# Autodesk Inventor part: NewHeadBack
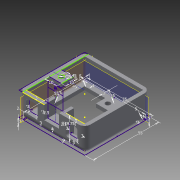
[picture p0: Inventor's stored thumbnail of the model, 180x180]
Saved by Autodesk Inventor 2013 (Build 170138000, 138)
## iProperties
Created: 2013-04
Part Number: NewHeadBack
Material: Generic
Document SubType Name: Modeling
Designer: frankenteddy
Density: 1 g/cm^3
Author: frankenteddy
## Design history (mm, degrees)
node "Blocks"
  sketch "Block1"
    geometry: L1 (49.279, 30.472)-(71.779, 30.472); L2 (71.779, 30.472)-(71.779, 18.072); L3 (71.779, 18.072)-(49.279, 18.072); L4 (49.279, 18.072)-(49.279, 30.472); L5 (49.279, 30.472)-(44.779, 30.472); L6 (44.779, 30.472)-(44.779, 18.072); L7 (44.779, 18.072)-(49.279, 18.072); L8 (49.279, 18.072)-(49.279, 30.472); L9 (71.779, 30.472)-(76.279, 30.472); L10 (76.279, 30.472)-(76.279, 18.072); L11 (76.279, 18.072)-(71.779, 18.072); L12 (71.779, 18.072)-(71.779, 30.472); L13 (44.779, 24.272)-(76.279, 24.272); L14 (60.529, 30.472)-(60.529, 18.072); L15 (47.029, 30.472)-(47.029, 18.072); L16 (74.029, 30.472)-(74.029, 18.072); C1 r 1.1 at (47.029, 24.272); C2 r 1.1 at (74.029, 24.272); 1 further point
    constraints: 32 end point, 8 midpoint, 6 parallel, 3 horizontal, 3 perpendicular, 2 centre point, 2 point on line
    dimensions: "d9" = 22.5 distance of L2.end L3.end; "d10" = 12.4 distance of L1.end L2.end; "d11" = 4.5 distance of L7.end L6.end; "d12" = 4.5 distance of L10.end L11.end; "d13" = 2.2 diameter of C1; "d14" = 2.2 diameter of C2; "d15" = 2.25 distance between parallel lines of L10 L16
sketch "Sketch1"
  geometry: L1 (-27.5, 27.5)-(27.5, 27.5); L2 (27.5, 27.5)-(27.5, -27.5); L3 (27.5, -27.5)-(-27.5, -27.5); L4 (-27.5, -27.5)-(-27.5, 27.5); L5 (-24.5, 24.5)-(24.5, 24.5); L6 (24.5, 24.5)-(24.5, -24.5); L7 (24.5, -24.5)-(-24.5, -24.5); L8 (-24.5, -24.5)-(-24.5, 24.5); L9 (-23.5, 27.5)-(-23.5, -27.5); L10 (-27.5, 23.5)-(27.5, 23.5); 5 further points
  constraints: 20 end point, 4 parallel, 4 perpendicular, 4 point on line, 2 coincident, 2 horizontal, 2 midpoint, 1 horizontal alignment, 1 vertical alignment
  dimensions: "d0" = 55 distance of L1.start L1.end; "d2" = 55 distance of L1.end L2.end; "d3" = 3 distance between parallel lines of L5 L1; "d4" = 3 distance between parallel lines of L8 L4; "d5" = 3 distance between parallel lines of L2 L6; "d6" = 3 distance between parallel lines of L3 L7; "d48" = 4 distance between parallel lines of L10 L1; "d49" = 4 distance between parallel lines of L4 L9
extrude "Extrusion1" new body sketch "Sketch1" distance "d7" = 19.75; taper "d8" = 0 deg
sketch "Sketch2"
  geometry: L1 (0, 0)-(49, 0) reference; L2 (49, -19.75)-(0, -19.75) reference; L3 (24.5, -19.75)-(24.5, 0); L4 (15.8, 0)-(15.8, -19.75); L5 (33.2, -19.75)-(33.2, 0); L6 (15.8, -19.75)-(33.2, -19.75); L7 (0, 0)-(0, -19.75) reference; L8 (49, 0)-(49, -19.75) reference; L9 (0, -3)-(15.8, -3); L10 (33.2, -3)-(49, -3); L11 (5, -6)-(10.8, -6); L12 (12.8, -8)-(12.8, -14.75); L13 (10.8, -16.75)-(5, -16.75); L14 (3, -14.75)-(3, -8); L15 (38.2, -6)-(44, -6); L16 (46, -8)-(46, -14.75); L17 (44, -16.75)-(38.2, -16.75); L18 (36.2, -14.75)-(36.2, -8); A1 r 2 centre (5, -8) between (5, -6) and (3, -8); A2 r 2 centre (10.8, -8) between (12.8, -8) and (10.8, -6); A3 r 2 centre (10.8, -14.75) between (10.8, -16.75) and (12.8, -14.75); A4 r 2 centre (5, -14.75) between (3, -14.75) and (5, -16.75); A5 r 2 centre (38.2, -8) between (38.2, -6) and (36.2, -8); A6 r 2 centre (44, -8) between (46, -8) and (44, -6); A7 r 2 centre (44, -14.75) between (44, -16.75) and (46, -14.75); A8 r 2 centre (38.2, -14.75) between (36.2, -14.75) and (38.2, -16.75)
  constraints: 28 end point, 16 point on circle, 16 tangent, 8 centre point, 8 point on line, 7 equal radius, 7 perpendicular, 4 parallel, 2 horizontal, 2 vertical, 1 midpoint
  dimensions: "d16" = 4 dimension on L1; "d17" = 19.75 dimension on L1 (derived); "d18" = 2.5 dimension on L4; "d19" = 2.5 dimension on L5; "d35" = 3 distance between parallel lines of L9 L1; "d36" = 3 distance between parallel lines of L10 L1; "d74" = 3 distance between parallel lines of L11 L9; "d75" = 3 distance between parallel lines of L7 L14; "d76" = 3 distance between parallel lines of L2 L13; "d77" = 3 distance between parallel lines of L4 L12; "d78" = 3 distance between parallel lines of L15 L10; "d79" = 3 distance between parallel lines of L16 L8; "d80" = 3 distance between parallel lines of L17 L2; "d81" = 3 distance between parallel lines of L18 L5; "d82" = 2 radius of A1
  node "Block1:1" dims "d16" = 4, "d17" = 19.75 (derived), "d18" = 2.5, "d19" = 2.5, "d35" = 3, "d36" = 3, "d74" = 3, "d75" = 3, "d76" = 3, "d77" = 3, "d78" = 3, "d79" = 3, "d80" = 3, "d81" = 3, "d82" = 2
extrude "Extrusion2" join sketch "Sketch2" distance "d20" = 7; taper "d21" = 0 deg
extrude "Extrusion3" cut sketch "Sketch2" distance "d22" = 7; taper "d23" = 0 deg
extrude "Extrusion4" cut sketch "Sketch2" distance "d24" = 3; taper "d25" = 0 deg
sketch "Sketch3"
  geometry: L1 (-27.5, -27.5)-(-6.2, -27.5) reference; L2 (-27.5, 27.5)-(-24.5, 27.5); L3 (-24.5, 27.5)-(-24.5, -27.5); L4 (-24.5, -27.5)-(-27.5, -27.5); L5 (-27.5, -27.5)-(-27.5, 27.5); L6 (-27.5, 0)-(0, 0); L7 (-24.5, 5)-(-14.5, 5); L8 (-14.5, 5)-(-14.5, -5); L9 (-14.5, -5)-(-24.5, -5); L10 (-24.5, -5)-(-24.5, 5); L11 (-19.5, 5)-(-19.5, -5); C1 r 2 at (-19.5, 0)
  constraints: 20 end point, 4 midpoint, 4 parallel, 3 perpendicular, 2 horizontal, 2 point on line, 1 centre point
  dimensions: "d26" = 10 distance of L8.end L9.end; "d27" = 10 distance of L7.end L8.end; "d28" = 5 distance between parallel lines of L7 L6; "d29" = 4 diameter of C1
extrude "Extrusion5" join sketch "Sketch3" distance "d30" = 3; taper "d31" = 0 deg
sketch "Sketch4"
  geometry: L1 (24.5, 5)-(14.5, 5); L2 (14.5, 5)-(14.5, -5); L3 (14.5, -5)-(24.5, -5); L4 (24.5, -5)-(24.5, 5); L5 (19.5, 5)-(19.5, -5); L6 (14.5, 0)-(24.5, 0); L7 (19.5, 4.879)-(23.725, 2.439); L8 (23.725, 2.439)-(23.725, -2.439); L9 (23.725, -2.439)-(19.5, -4.879); L10 (19.5, -4.879)-(15.275, -2.439); L11 (15.275, -2.439)-(15.275, 2.439); L12 (15.275, 2.439)-(19.5, 4.879); C1 r 2 at (19.5, 0) reference; 2 further points
  constraints: 24 end point, 4 midpoint, 2 parallel, 1 coincident, 1 horizontal, 1 perpendicular, 1 point on line, 13 other
  dimensions: "d32" = 8.45 distance between parallel lines of L8 L11
extrude "Extrusion7" join sketch "Sketch2" distance "d37" = 5; taper "d38" = 0 deg
sketch "Sketch5"
  geometry: L1 (0, 0)-(-19.75, 0) reference; L2 (0, 49)-(0, 0) reference; L3 (0, 49)-(-19.75, 49) reference; L4 (-3, 49)-(-3, 0); 1 further point
  constraints: 2 end point, 2 point on line, 1 perpendicular
  dimensions: "d39" = 3 distance between parallel lines of L4 L2
extrude "Extrusion8" join sketch "Sketch5" distance "d40" = 5; taper "d41" = 0 deg
sketch "Sketch6"
  geometry: L1 (49, 0)-(0, 0) reference; L2 (49, 0)-(49, 19.75) reference; L3 (0, 0)-(0, 19.75) reference; L4 (0, 3)-(49, 3); 1 further point
  constraints: 2 end point, 2 point on line, 1 perpendicular
  dimensions: "d42" = 3 distance between parallel lines of L4 L1
extrude "Extrusion9" join sketch "Sketch6" distance "d43" = 5; taper "d44" = 0 deg
mirror "Mirror1"
fillet "Fillet5" dims "d69" = 3
fillet "Fillet2" dims "d46" = 5
workplane "Work Plane1"
workplane "Work Plane2"
sketch "Sketch7"
  geometry: L1 (0, 0)-(-55, 0) reference; L2 (-55, 0)-(-55, 1); L3 (-55, 1)-(0, 1); L4 (0, 1)-(0, 0) reference; L5 (-4, 1)-(-4, 0); L6 (-51, 1)-(-51, 0); L7 (-27.5, 1)-(-27.5, 0); L8 (-27.5, 3.5)-(-27.5, -1.5); L9 (-4, 3.5)-(-4, -1.5); L10 (-51, 3.5)-(-51, -1.5); A1 r 2.5 centre (-51, 1) between (-51, 3.5) and (-51, -1.5); A2 r 2.5 centre (-4, 1) between (-4, 3.5) and (-4, -1.5); A3 r 2.5 centre (-27.5, 1) between (-27.5, 3.5) and (-27.5, -1.5)
  constraints: 20 end point, 6 point on circle, 4 parallel, 4 point on line, 3 centre point, 3 coincident, 3 perpendicular, 2 horizontal, 1 collinear, 1 midpoint, 1 vertical
  dimensions: "d51" = 55 distance of L2.end L3.end; "d52" = 1 distance of L1.end L2.end; "d53" = 4 distance between parallel lines of L5 L4; "d54" = 4 distance between parallel lines of L2 L6; "d55" = 5 diameter of A1; "d56" = 5 diameter of A2; "d57" = 5 diameter of A3
sketch "Sketch8"
  geometry: L1 (0, 0)-(-55, 0) reference; L2 (-55, 0)-(-55, 1); L3 (-55, 1)-(0, 1); L4 (0, 1)-(0, 0) reference; L5 (-27.5, 1)-(-27.5, 0); L6 (-27.5, 3.5)-(-27.5, -1.5); A1 r 2.5 centre (-27.5, 1) between (-27.5, 3.5) and (-27.5, -1.5)
  constraints: 12 end point, 2 horizontal, 2 parallel, 2 point on circle, 1 centre point, 1 coincident, 1 collinear, 1 midpoint, 1 perpendicular, 1 vertical
  dimensions: "d61" = 55 distance of L2.end L3.end; "d62" = 1 distance of L1.end L2.end; "d63" = 5 diameter of A1
extrude "Extrusion10" cut sketch "Sketch2" distance "d65" = 6; taper "d66" = 0 deg
extrude "Extrusion13" cut sketch "Sketch2" distance "d83" = 3; taper "d84" = 0 deg
body "Solid1"
